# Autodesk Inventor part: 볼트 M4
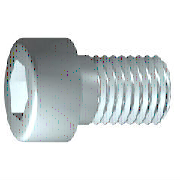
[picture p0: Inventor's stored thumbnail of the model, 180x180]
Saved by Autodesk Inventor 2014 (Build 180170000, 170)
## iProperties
IsCustomPart: 0
Created: 2012-02
Part Number: 볼트 M4
Material: 스테인리스강
Description: 6각 소켓 머리 캡 나사
Document SubType Name: Modeling
Standard: ISO 4762
Designer: mduedu
Standard Revision: Fourth edition 2004-03-01
Standards Organization: ISO
Language: ko-KR
Size Designation: M4 x 12
Categories: <MemberInstance><Categories><Category DisplayName="조임쇠" InternalName="e4da775c-781d-43d5-af7c-5136215cf5a6" Mnemonic="FSTN"><Category DisplayName="볼트" InternalN
Density: 8.08 g/cm^3
Mass: 2.2972 g
Surface Area: 3.30853 cm^2
Volume: 0.284306 cm^3
Appearance: 반광택
Author: mduedu
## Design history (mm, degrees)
sketch "스케치1"
  geometry: L1 (-1, 0)-(12, 0); L2 (12, 0)-(12, 2); L3 (12, 2)-(1.75, 2); L4 (1.75, 2)-(1.32, 2); L5 (1.32, 2)-(0, 2); L6 (0, 2)-(0, 3.5); L7 (0, 3.5)-(-4, 3.5); L8 (-4, 3.5)-(-4, 1.732); L9 (-4, 1.732)-(-2, 1.732); L10 (-2, 1.732)-(-1, 0); L11 (-7.2, 0)-(15.2, 0) reference; L12 (0, -0.7)-(0, 4.2) reference; L13 (1.75, 2)-(0, 2)
  constraints: 22 end point, 6 parallel, 2 collinear, 2 perpendicular, 1 horizontal, 1 point on line
  dimensions: "d1" = 10.25 distance from line of L3.end L2 (= GEL); "d2" = 0.42952 distance of L4.end L3.end (computed from GAL); "d3" = 4 distance between parallel lines of L8 L6 (= KOH); "d4" = 2 distance of L8.end L9.end (= INTI); "d5" = 60 deg angle of L10 L1; "d6" = 4 diameter of L3 L1 (= GD); "d7" = 4 diameter of L5 L1 (= BDM); "d8" = 3.4641 diameter of L9 L1 (= 1.1547 x SW); "d9" = 7 diameter of L7 L1 (= KOD); "d26" = 12 distance between parallel lines of L12 L2 (= NLG)
revolve "본체" sketch "스케치1" stored, may be unused: angle "d10" = 90 deg
sketch "스케치2"
  geometry: L1 (0, -4.9)-(0, 4.9) reference; L2 (-4.9, 0)-(4.9, 0) reference; L3 (1.732, 0)-(0.866, -1.5); L4 (0.866, -1.5)-(-0.866, -1.5); L5 (-0.866, -1.5)-(-1.732, 0); L6 (-1.732, 0)-(-0.866, 1.5); L7 (-0.866, 1.5)-(0.866, 1.5); L8 (0.866, 1.5)-(1.732, 0); 2 further points
  constraints: 12 end point, 1 coincident, 1 horizontal alignment, 1 point on line, 12 other
extrude "슬롯" join sketch "스케치2" stored distance "d11" = 10; taper "d12" = 0 deg
workplane "Work Plane1"
fillet "Fillet2" dims "d30" = 0.1 (= R)
body "Solid1"
fillet "모깎기1" dims "d17" = 0.4 (= RR)
feature "스레드" dims "d13" = 10.25 (= GEL), "d14" = 0
chamfer "모따기1" distance "d15" = 0.42941 (= -0.5 x SPD + 0.5 x GD); stored, may be unused: second distance "d16" = 0.42941 (= GUL), angle "d27" = 45 deg
other parameters: "GD" = 4 [user parameter; used in 2 equation terms], "NLG" = 12 [user parameter; used in 1 equation term], "GEL" = 10.25 [user parameter; used in 2 equation terms], "KOD" = 7 [user parameter; used in 1 equation term], "KOH" = 4 [user parameter; used in 1 equation term], "INTI" = 2 [user parameter; used in 1 equation term], "GAL" = 0.42941 (= 0.61345 x PTC) [user parameter; used in 1 equation term], "GUL" = 0.42941 (= 0.61345 x PTC) [user parameter; used in 1 equation term], "BDM" = 4 (= NND) [user parameter; used in 1 equation term], "SW" = 3 [user parameter; used in 2 equation terms], "RR" = 0.4 [user parameter; used in 1 equation term], "SPD" = 3.14117 (= NND - 1.2269 x PTC) [user parameter; used in 1 equation term], "d19" = 0, "d28" = 0, "d29" = 0, "R" = 0.1 [user parameter; used in 1 equation term], "TOA" = 30 deg [user parameter], "GD1" = 3.14117 (= THREADDIA - 1.2269 x PTC) [user parameter], "THREADDIA" = 4 [user parameter; used in 1 equation term], "FAWI" = 45 deg [user parameter], "TPU" = 14.28571 (computed from PTC) [user parameter], "PTC" = 0.7 [user parameter; used in 5 equation terms], "NND" = 4 [user parameter; used in 2 equation terms], "E0" = 3.465 (= 1.155 x SW) [user parameter]
